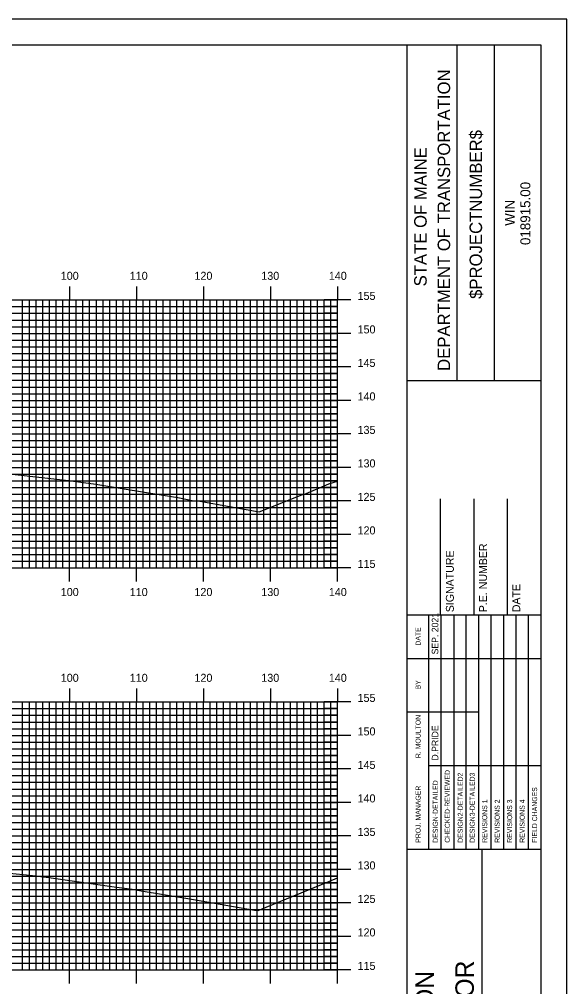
# Model space of a CAD drawing. Extents: x 851926 to 852269, y 366605 to 366825.
# Drawn here: x 852184.5 to 852266.2, y 366680.6 to 366824.9 of the extents above; entities that cross this region are included whole.
import ezdxf

# ---------------------------------------------------------------- set-up
doc = ezdxf.new("R2010")
doc.units = 0
for name, color, linetype in [('BORDER', 7, 'Continuous'), ('H_V ANNOTATION', 7, 'Continuous'), ('MAJOR', 7, 'Continuous'), ('MINOR', 7, 'Continuous'), ('PLOT BOUNDARY', 7, 'Continuous'), ('S_Roadway_Centerline', 7, 'Continuous')]:
    doc.layers.add(name, color=color, linetype=linetype)

msp = doc.modelspace()

# ---------------------------------------------------------------- linework, layer by layer
at = {"layer": 'BORDER'}
for p, q in [((852242.36, 366611.06), (852242.36, 366821.06)), ((852249.82, 366771.05), (852249.82, 366821.05)), ((852255.41, 366771.05), (852255.41, 366821.05)), ((852242.37, 366771.04), (852262.36, 366771.04)), ((852247.36, 366736.06), (852247.36, 366753.36)), ((852252.36, 366736.06), (852252.36, 366753.36)), ((852257.36, 366736.06), (852257.36, 366753.36)), ((852242.36, 366736.06), (852262.36, 366736.06)), ((852242.36, 366701.06), (852262.36, 366701.06)), ((852253.55, 366631.06), (852253.55, 366701.06))]:
    msp.add_line(p, q, dxfattribs=at)
msp.add_lwpolyline([(851942.36, 366611.06), (852262.36, 366611.06), (852262.36, 366821.06), (851942.36, 366821.06)], close=True, dxfattribs=at)
for points in [[(852245.59, 366729.56), (852245.59, 366736.06)], [(852247.46, 366701.07), (852247.46, 366736.06)], [(852249.32, 366736.06), (852249.32, 366701.07)], [(852251.19, 366701.07), (852251.19, 366736.06)], [(852253.05, 366701.07), (852253.05, 366736.06)], [(852254.91, 366701.07), (852254.91, 366736.06)], [(852256.78, 366701.07), (852256.78, 366736.06)], [(852258.64, 366701.07), (852258.64, 366736.06)], [(852260.5, 366701.07), (852260.5, 366736.06)], [(852245.6, 366701.07), (852245.6, 366734.65)], [(852242.36, 366729.56), (852262.36, 366729.56)], [(852242.36, 366721.56), (852245.6, 366721.56)], [(852245.59, 366721.56), (852253.05, 366721.56)], [(852245.59, 366713.56), (852262.36, 366713.56)]]:
    msp.add_lwpolyline(points, dxfattribs=at)
at = {"layer": 'MAJOR'}
for p, q in [((852191.96, 366785.06), (852191.96, 366783.06)), ((852201.96, 366785.06), (852201.96, 366783.06)), ((852211.96, 366785.06), (852211.96, 366783.06)), ((852221.96, 366785.06), (852221.96, 366783.06)), ((852231.96, 366785.06), (852231.96, 366783.06)), ((851951.96, 366783.06), (852231.96, 366783.06)), ((851951.96, 366783.06), (852231.96, 366783.06)), ((852191.96, 366743.06), (852191.96, 366783.06)), ((852201.96, 366743.06), (852201.96, 366783.06)), ((852211.96, 366743.06), (852211.96, 366783.06)), ((852221.96, 366743.06), (852221.96, 366783.06)), ((852233.97, 366783.06), (852229.96, 366783.06)), ((852231.96, 366743.06), (852231.96, 366783.06)), ((852231.96, 366743.06), (852231.96, 366783.06)), ((851951.96, 366778.06), (852231.96, 366778.06)), ((852233.97, 366778.06), (852229.96, 366778.06)), ((851951.96, 366773.06), (852231.96, 366773.06)), ((852233.97, 366773.06), (852229.96, 366773.06)), ((851951.96, 366768.06), (852231.96, 366768.06)), ((852233.97, 366768.06), (852229.96, 366768.06)), ((851951.96, 366763.06), (852231.96, 366763.06)), ((852233.97, 366763.06), (852229.96, 366763.06)), ((851951.96, 366758.06), (852231.96, 366758.06)), ((852233.97, 366758.06), (852229.96, 366758.06)), ((851951.96, 366753.06), (852231.96, 366753.06)), ((852233.97, 366753.06), (852229.96, 366753.06)), ((851951.96, 366748.06), (852231.96, 366748.06)), ((852233.97, 366748.06), (852229.96, 366748.06)), ((851951.96, 366743.06), (852231.96, 366743.06)), ((851951.96, 366743.06), (852231.96, 366743.06)), ((852191.96, 366741.05), (852191.96, 366743.06)), ((852201.96, 366741.05), (852201.96, 366743.06)), ((852211.96, 366741.05), (852211.96, 366743.06)), ((852221.96, 366741.05), (852221.96, 366743.06)), ((852233.97, 366743.06), (852229.96, 366743.06)), ((852231.96, 366741.05), (852231.96, 366743.06)), ((852191.96, 366725.06), (852191.96, 366723.06)), ((852201.96, 366725.06), (852201.96, 366723.06)), ((852211.96, 366725.06), (852211.96, 366723.06)), ((852221.96, 366725.06), (852221.96, 366723.06)), ((852231.96, 366725.06), (852231.96, 366723.06)), ((851951.96, 366723.06), (852231.96, 366723.06)), ((851951.96, 366723.06), (852231.96, 366723.06)), ((852191.96, 366683.06), (852191.96, 366723.06)), ((852201.96, 366683.06), (852201.96, 366723.06)), ((852211.96, 366683.06), (852211.96, 366723.06)), ((852221.96, 366683.06), (852221.96, 366723.06)), ((852233.97, 366723.06), (852229.96, 366723.06)), ((852231.96, 366683.06), (852231.96, 366723.06)), ((852231.96, 366683.06), (852231.96, 366723.06)), ((851951.96, 366718.06), (852231.96, 366718.06)), ((852233.97, 366718.06), (852229.96, 366718.06)), ((851951.96, 366713.06), (852231.96, 366713.06)), ((852233.97, 366713.06), (852229.96, 366713.06)), ((851951.96, 366708.06), (852231.96, 366708.06)), ((852233.97, 366708.06), (852229.96, 366708.06)), ((851951.96, 366703.06), (852231.96, 366703.06)), ((852233.97, 366703.06), (852229.96, 366703.06)), ((851951.96, 366698.06), (852231.96, 366698.06)), ((852233.97, 366698.06), (852229.96, 366698.06)), ((851951.96, 366693.06), (852231.96, 366693.06)), ((852233.97, 366693.06), (852229.96, 366693.06)), ((851951.96, 366688.06), (852231.96, 366688.06)), ((852233.97, 366688.06), (852229.96, 366688.06)), ((851951.96, 366683.06), (852231.96, 366683.06)), ((851951.96, 366683.06), (852231.96, 366683.06)), ((852191.96, 366681.05), (852191.96, 366683.06)), ((852201.96, 366681.05), (852201.96, 366683.06)), ((852211.96, 366681.05), (852211.96, 366683.06)), ((852221.96, 366681.05), (852221.96, 366683.06)), ((852233.97, 366683.06), (852229.96, 366683.06)), ((852231.96, 366681.05), (852231.96, 366683.06))]:
    msp.add_line(p, q, dxfattribs=at)
at = {"layer": 'MINOR'}
for p, q in [((852184.96, 366743.06), (852184.96, 366783.06)), ((852185.96, 366743.06), (852185.96, 366783.06)), ((852186.96, 366743.06), (852186.96, 366783.06)), ((852187.96, 366743.06), (852187.96, 366783.06)), ((852188.96, 366743.06), (852188.96, 366783.06)), ((852189.96, 366743.06), (852189.96, 366783.06)), ((852190.96, 366743.06), (852190.96, 366783.06)), ((852192.96, 366743.06), (852192.96, 366783.06)), ((852193.96, 366743.06), (852193.96, 366783.06)), ((852194.96, 366743.06), (852194.96, 366783.06)), ((852195.96, 366743.06), (852195.96, 366783.06)), ((852196.96, 366743.06), (852196.96, 366783.06)), ((852197.96, 366743.06), (852197.96, 366783.06)), ((852198.96, 366743.06), (852198.96, 366783.06)), ((852199.96, 366743.06), (852199.96, 366783.06)), ((852200.96, 366743.06), (852200.96, 366783.06)), ((852202.96, 366743.06), (852202.96, 366783.06)), ((852203.96, 366743.06), (852203.96, 366783.06)), ((852204.96, 366743.06), (852204.96, 366783.06)), ((852205.96, 366743.06), (852205.96, 366783.06)), ((852206.96, 366743.06), (852206.96, 366783.06)), ((852207.96, 366743.06), (852207.96, 366783.06)), ((852208.96, 366743.06), (852208.96, 366783.06)), ((852209.96, 366743.06), (852209.96, 366783.06)), ((852210.96, 366743.06), (852210.96, 366783.06)), ((852212.96, 366743.06), (852212.96, 366783.06)), ((852213.96, 366743.06), (852213.96, 366783.06)), ((852214.96, 366743.06), (852214.96, 366783.06)), ((852215.96, 366743.06), (852215.96, 366783.06)), ((852216.96, 366743.06), (852216.96, 366783.06)), ((852217.96, 366743.06), (852217.96, 366783.06)), ((852218.96, 366743.06), (852218.96, 366783.06)), ((852219.96, 366743.06), (852219.96, 366783.06)), ((852220.96, 366743.06), (852220.96, 366783.06)), ((852222.96, 366743.06), (852222.96, 366783.06)), ((852223.96, 366743.06), (852223.96, 366783.06)), ((852224.96, 366743.06), (852224.96, 366783.06)), ((852225.96, 366743.06), (852225.96, 366783.06)), ((852226.96, 366743.06), (852226.96, 366783.06)), ((852227.96, 366743.06), (852227.96, 366783.06)), ((852228.96, 366743.06), (852228.96, 366783.06)), ((852229.96, 366743.06), (852229.96, 366783.06)), ((852230.96, 366743.06), (852230.96, 366783.06)), ((851951.96, 366782.06), (852231.96, 366782.06)), ((852231.96, 366782.06), (852229.96, 366782.06)), ((851951.96, 366781.06), (852231.96, 366781.06)), ((851951.96, 366780.06), (852231.96, 366780.06)), ((852231.96, 366781.06), (852229.96, 366781.06)), ((852231.96, 366780.06), (852229.96, 366780.06)), ((851951.96, 366779.06), (852231.96, 366779.06)), ((852231.96, 366779.06), (852229.96, 366779.06)), ((851951.96, 366777.06), (852231.96, 366777.06)), ((852231.96, 366777.06), (852229.96, 366777.06)), ((851951.96, 366776.06), (852231.96, 366776.06)), ((852231.96, 366776.06), (852229.96, 366776.06)), ((851951.96, 366775.06), (852231.96, 366775.06)), ((851951.96, 366774.06), (852231.96, 366774.06)), ((852231.96, 366775.06), (852229.96, 366775.06)), ((852231.96, 366774.06), (852229.96, 366774.06)), ((851951.96, 366772.06), (852231.96, 366772.06)), ((852231.96, 366772.06), (852229.96, 366772.06)), ((851951.96, 366771.06), (852231.96, 366771.06)), ((851951.96, 366770.06), (852231.96, 366770.06)), ((852231.96, 366771.06), (852229.96, 366771.06)), ((852231.96, 366770.06), (852229.96, 366770.06)), ((851951.96, 366769.06), (852231.96, 366769.06)), ((852231.96, 366769.06), (852229.96, 366769.06)), ((851951.96, 366767.06), (852231.96, 366767.06)), ((852231.96, 366767.06), (852229.96, 366767.06)), ((851951.96, 366766.06), (852231.96, 366766.06)), ((852231.96, 366766.06), (852229.96, 366766.06)), ((851951.96, 366765.06), (852231.96, 366765.06)), ((851951.96, 366764.06), (852231.96, 366764.06)), ((852231.96, 366765.06), (852229.96, 366765.06)), ((852231.96, 366764.06), (852229.96, 366764.06)), ((851951.96, 366762.06), (852231.96, 366762.06)), ((851951.96, 366761.06), (852231.96, 366761.06)), ((852231.96, 366762.06), (852229.96, 366762.06)), ((852231.96, 366761.06), (852229.96, 366761.06)), ((851951.96, 366760.06), (852231.96, 366760.06)), ((852231.96, 366760.06), (852229.96, 366760.06)), ((851951.96, 366759.06), (852231.96, 366759.06)), ((852231.96, 366759.06), (852229.96, 366759.06)), ((851951.96, 366757.06), (852231.96, 366757.06)), ((852231.96, 366757.06), (852229.96, 366757.06)), ((851951.96, 366756.06), (852231.96, 366756.06)), ((852231.96, 366756.06), (852229.96, 366756.06)), ((851951.96, 366755.06), (852231.96, 366755.06)), ((851951.96, 366754.06), (852231.96, 366754.06)), ((852231.96, 366755.06), (852229.96, 366755.06)), ((852231.96, 366754.06), (852229.96, 366754.06)), ((851951.96, 366752.06), (852231.96, 366752.06)), ((851951.96, 366751.06), (852231.96, 366751.06)), ((852231.96, 366752.06), (852229.96, 366752.06)), ((852231.96, 366751.06), (852229.96, 366751.06)), ((851951.96, 366750.06), (852231.96, 366750.06)), ((852231.96, 366750.06), (852229.96, 366750.06)), ((851951.96, 366749.06), (852231.96, 366749.06)), ((852231.96, 366749.06), (852229.96, 366749.06)), ((851951.96, 366747.06), (852231.96, 366747.06)), ((852231.96, 366747.06), (852229.96, 366747.06)), ((851951.96, 366746.06), (852231.96, 366746.06)), ((852231.96, 366746.06), (852229.96, 366746.06)), ((851951.96, 366745.06), (852231.96, 366745.06)), ((851951.96, 366744.06), (852231.96, 366744.06)), ((852231.96, 366745.06), (852229.96, 366745.06)), ((852231.96, 366744.06), (852229.96, 366744.06)), ((851951.96, 366722.06), (852231.96, 366722.06)), ((852184.96, 366683.06), (852184.96, 366723.06)), ((852185.96, 366683.06), (852185.96, 366723.06)), ((852186.96, 366683.06), (852186.96, 366723.06)), ((852187.96, 366683.06), (852187.96, 366723.06)), ((852188.96, 366683.06), (852188.96, 366723.06)), ((852189.96, 366683.06), (852189.96, 366723.06)), ((852190.96, 366683.06), (852190.96, 366723.06)), ((852192.96, 366683.06), (852192.96, 366723.06)), ((852193.96, 366683.06), (852193.96, 366723.06)), ((852194.96, 366683.06), (852194.96, 366723.06)), ((852195.96, 366683.06), (852195.96, 366723.06)), ((852196.96, 366683.06), (852196.96, 366723.06)), ((852197.96, 366683.06), (852197.96, 366723.06)), ((852198.96, 366683.06), (852198.96, 366723.06)), ((852199.96, 366683.06), (852199.96, 366723.06)), ((852200.96, 366683.06), (852200.96, 366723.06)), ((852202.96, 366683.06), (852202.96, 366723.06)), ((852203.96, 366683.06), (852203.96, 366723.06)), ((852204.96, 366683.06), (852204.96, 366723.06)), ((852205.96, 366683.06), (852205.96, 366723.06)), ((852206.96, 366683.06), (852206.96, 366723.06)), ((852207.96, 366683.06), (852207.96, 366723.06)), ((852208.96, 366683.06), (852208.96, 366723.06)), ((852209.96, 366683.06), (852209.96, 366723.06)), ((852210.96, 366683.06), (852210.96, 366723.06)), ((852212.96, 366683.06), (852212.96, 366723.06)), ((852213.96, 366683.06), (852213.96, 366723.06)), ((852214.96, 366683.06), (852214.96, 366723.06)), ((852215.96, 366683.06), (852215.96, 366723.06)), ((852216.96, 366683.06), (852216.96, 366723.06)), ((852217.96, 366683.06), (852217.96, 366723.06)), ((852218.96, 366683.06), (852218.96, 366723.06)), ((852219.96, 366683.06), (852219.96, 366723.06)), ((852220.96, 366683.06), (852220.96, 366723.06)), ((852222.96, 366683.06), (852222.96, 366723.06)), ((852223.96, 366683.06), (852223.96, 366723.06)), ((852224.96, 366683.06), (852224.96, 366723.06)), ((852225.96, 366683.06), (852225.96, 366723.06)), ((852226.96, 366683.06), (852226.96, 366723.06)), ((852227.96, 366683.06), (852227.96, 366723.06)), ((852228.96, 366683.06), (852228.96, 366723.06)), ((852229.96, 366683.06), (852229.96, 366723.06)), ((852231.96, 366722.06), (852229.96, 366722.06)), ((852230.96, 366683.06), (852230.96, 366723.06)), ((851951.96, 366721.06), (852231.96, 366721.06)), ((852231.96, 366721.06), (852229.96, 366721.06)), ((851951.96, 366720.06), (852231.96, 366720.06)), ((852231.96, 366720.06), (852229.96, 366720.06)), ((851951.96, 366719.06), (852231.96, 366719.06)), ((852231.96, 366719.06), (852229.96, 366719.06)), ((851951.96, 366717.06), (852231.96, 366717.06)), ((852231.96, 366717.06), (852229.96, 366717.06)), ((851951.96, 366716.06), (852231.96, 366716.06)), ((851951.96, 366715.06), (852231.96, 366715.06)), ((852231.96, 366716.06), (852229.96, 366716.06)), ((852231.96, 366715.06), (852229.96, 366715.06)), ((851951.96, 366714.06), (852231.96, 366714.06)), ((852231.96, 366714.06), (852229.96, 366714.06)), ((851951.96, 366712.06), (852231.96, 366712.06)), ((852231.96, 366712.06), (852229.96, 366712.06)), ((851951.96, 366711.06), (852231.96, 366711.06)), ((852231.96, 366711.06), (852229.96, 366711.06)), ((851951.96, 366710.06), (852231.96, 366710.06)), ((851951.96, 366709.06), (852231.96, 366709.06)), ((852231.96, 366710.06), (852229.96, 366710.06)), ((852231.96, 366709.06), (852229.96, 366709.06)), ((851951.96, 366707.06), (852231.96, 366707.06)), ((852231.96, 366707.06), (852229.96, 366707.06)), ((851951.96, 366706.06), (852231.96, 366706.06)), ((851951.96, 366705.06), (852231.96, 366705.06)), ((852231.96, 366706.06), (852229.96, 366706.06)), ((852231.96, 366705.06), (852229.96, 366705.06)), ((851951.96, 366704.06), (852231.96, 366704.06)), ((852231.96, 366704.06), (852229.96, 366704.06)), ((851951.96, 366702.06), (852231.96, 366702.06)), ((852231.96, 366702.06), (852229.96, 366702.06)), ((851951.96, 366701.06), (852231.96, 366701.06)), ((852231.96, 366701.06), (852229.96, 366701.06)), ((851951.96, 366700.06), (852231.96, 366700.06)), ((851951.96, 366699.06), (852231.96, 366699.06)), ((852231.96, 366700.06), (852229.96, 366700.06)), ((852231.96, 366699.06), (852229.96, 366699.06)), ((851951.96, 366697.06), (852231.96, 366697.06)), ((851951.96, 366696.06), (852231.96, 366696.06)), ((852231.96, 366697.06), (852229.96, 366697.06)), ((852231.96, 366696.06), (852229.96, 366696.06)), ((851951.96, 366695.06), (852231.96, 366695.06)), ((852231.96, 366695.06), (852229.96, 366695.06)), ((851951.96, 366694.06), (852231.96, 366694.06)), ((852231.96, 366694.06), (852229.96, 366694.06)), ((851951.96, 366692.06), (852231.96, 366692.06)), ((852231.96, 366692.06), (852229.96, 366692.06)), ((851951.96, 366691.06), (852231.96, 366691.06)), ((852231.96, 366691.06), (852229.96, 366691.06)), ((851951.96, 366690.06), (852231.96, 366690.06)), ((851951.96, 366689.06), (852231.96, 366689.06)), ((852231.96, 366690.06), (852229.96, 366690.06)), ((852231.96, 366689.06), (852229.96, 366689.06)), ((851951.96, 366687.06), (852231.96, 366687.06)), ((851951.96, 366686.06), (852231.96, 366686.06)), ((852231.96, 366687.06), (852229.96, 366687.06)), ((852231.96, 366686.06), (852229.96, 366686.06)), ((851951.96, 366685.06), (852231.96, 366685.06)), ((852231.96, 366685.06), (852229.96, 366685.06)), ((851951.96, 366684.06), (852231.96, 366684.06)), ((852231.96, 366684.06), (852229.96, 366684.06))]:
    msp.add_line(p, q, dxfattribs=at)
at = {"layer": 'PLOT BOUNDARY'}
msp.add_lwpolyline([(851926.18, 366604.94), (852266.18, 366604.94), (852266.18, 366824.94), (851926.18, 366824.94)], close=True, dxfattribs=at)
at = {"layer": 'S_Roadway_Centerline'}
for points in [[(852182.95, 366757.11), (852189.15, 366756.39), (852191.81, 366756.1), (852195.9, 366755.55), (852203.43, 366754.33), (852208.11, 366753.57), (852210.51, 366753.08), (852211.43, 366753), (852220.29, 366751.43), (852226.63, 366753.95), (852226.93, 366754.01), (852230.65, 366755.62), (852231.96, 366756.02)], [(852183.01, 366697.51), (852186.05, 366697.2), (852188.87, 366696.84), (852198.6, 366695.47), (852201.33, 366695.1), (852202.66, 366694.88), (852209.64, 366693.71), (852219.58, 366691.97), (852220.12, 366691.94), (852221.3, 366692.43), (852230.67, 366696.27), (852231.96, 366696.8)]]:
    msp.add_lwpolyline(points, dxfattribs=at)

# ---------------------------------------------------------------- texts
at = {"layer": 'BORDER'}
for s, height, p in [('DEPARTMENT OF TRANSPORTATION', 1.8635, (852248.78, 366772.47)), ('$PROJECTNUMBER$', 1.8635, (852253.55, 366783.21)), ('STATE OF MAINE', 1.8635, (852245.28, 366785.08)), ('018915.00', 1.491, (852260.76, 366791.25)), ('WIN', 1.491, (852258.44, 366794.12)), ('P.E. NUMBER', 1.1811, (852254.29, 366736.45)), ('SIGNATURE', 1.181, (852249.33, 366736.45)), ('DATE', 1.181, (852259.25, 366736.45)), ('SEP. 2021', 0.969, (852247.01, 366730.15)), ('DATE', 0.743, (852244.37, 366731.47)), ('BY', 0.743, (852244.37, 366724.93)), ('R. MOULTON', 0.745, (852244.37, 366714.67)), ('D.PRIDE', 0.969, (852247.01, 366714.31)), ('CHECKED-REVIEWED', 0.7455, (852248.73, 366702.04)), ('DESIGN2-DETAILED2', 0.7455, (852250.66, 366702.04)), ('DESIGN3-DETAILED3', 0.7455, (852252.45, 366702.04)), ('DESIGN-DETAILED', 0.7455, (852246.94, 366702.04)), ('PROJ. MANAGER', 0.7455, (852244.37, 366702.04)), ('FIELD CHANGES', 0.7455, (852261.77, 366702.04)), ('REVISIONS 1', 0.7455, (852254.32, 366702.04)), ('REVISIONS 2', 0.7455, (852256.18, 366702.04)), ('REVISIONS 3', 0.7455, (852258.04, 366702.04)), ('REVISIONS 4', 0.7455, (852259.91, 366702.04)), ('1-395/ROUTE 9 CONNECTOR', 2.7557, (852252.32, 366633.26)), ('BREWER TO EDDINGTON', 2.7557, (852246.35, 366637.46))]:
    msp.add_text(s, height=height, rotation=90, dxfattribs=at).set_placement(p)
at = {"layer": 'H_V ANNOTATION'}
for s, p in [('100', (852190.65, 366786.06)), ('110', (852200.95, 366786.06)), ('120', (852210.61, 366786.06)), ('130', (852220.59, 366786.06)), ('140', (852230.67, 366786.06)), ('155', (852234.96, 366783.06)), ('150', (852234.96, 366778.06)), ('145', (852234.96, 366773.06)), ('140', (852234.96, 366768.06)), ('135', (852234.96, 366763.06)), ('130', (852234.96, 366758.06)), ('125', (852234.96, 366753.06)), ('120', (852234.96, 366748.06)), ('115', (852234.96, 366743.06)), ('100', (852190.65, 366738.86)), ('110', (852200.95, 366738.86)), ('120', (852210.61, 366738.86)), ('130', (852220.59, 366738.86)), ('140', (852230.67, 366738.86)), ('100', (852190.65, 366726.06)), ('110', (852200.95, 366726.06)), ('120', (852210.61, 366726.06)), ('130', (852220.59, 366726.06)), ('140', (852230.67, 366726.06)), ('155', (852234.96, 366723.06)), ('150', (852234.96, 366718.06)), ('145', (852234.96, 366713.06)), ('140', (852234.96, 366708.06)), ('135', (852234.96, 366703.06)), ('130', (852234.96, 366698.06)), ('125', (852234.96, 366693.06)), ('120', (852234.96, 366688.06)), ('115', (852234.96, 366683.06))]:
    msp.add_text(s, height=1.2, dxfattribs=at).set_placement(p)

doc.saveas('drawing.dxf')
